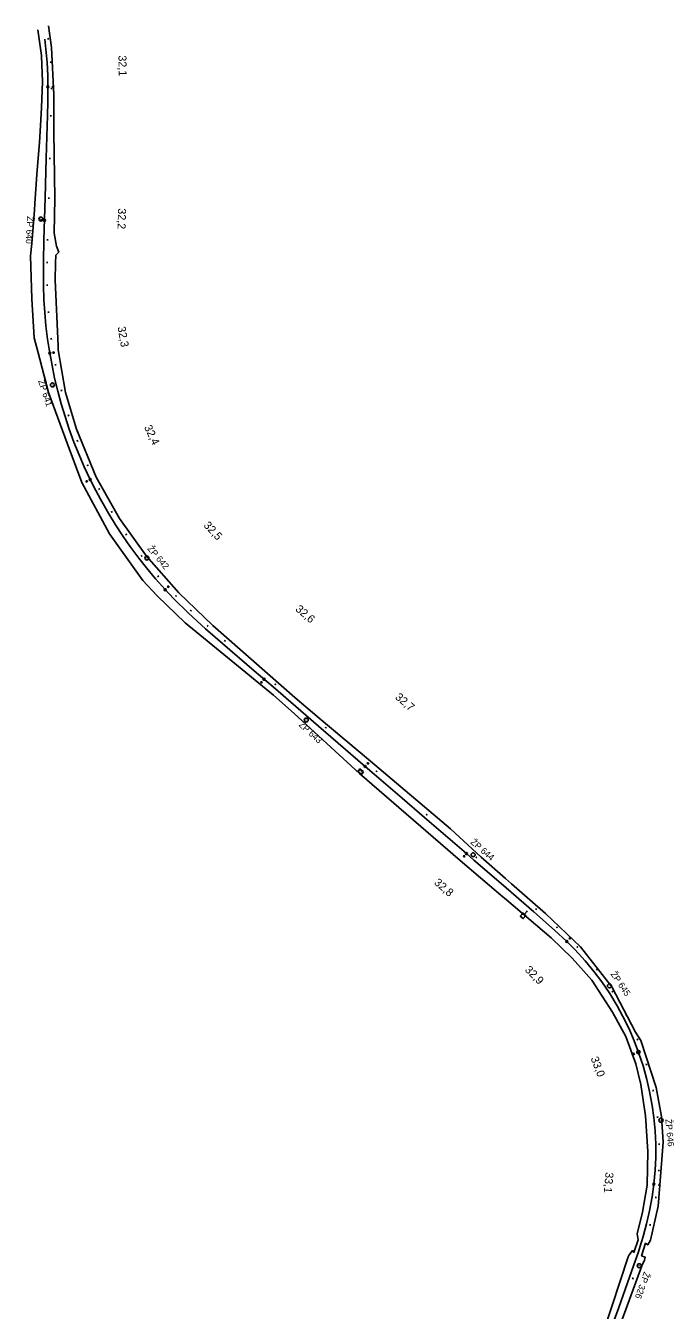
# Model space of a CAD drawing. Extents: x -792643 to -787072, y -1118436 to -1109677.
# Drawn here: x -787716 to -787231, y -1117454 to -1116491 of the extents above; entities that cross this region are included whole.
import ezdxf

# ---------------------------------------------------------------- set-up
doc = ezdxf.new("R2010")
doc.units = 0
for name, color, linetype in [('Vrstva 1', 7, 'Continuous'), ('Vrstva 53', 7, 'Continuous'), ('Vrstva 55', 7, 'Continuous'), ('Vrstva 63', 7, 'Continuous'), ('Vrstva 7', 7, 'Continuous')]:
    doc.layers.add(name, color=color, linetype=linetype)

msp = doc.modelspace()

# ---------------------------------------------------------------- linework, layer by layer
at = {"layer": 'Vrstva 1'}
msp.add_line((-787264.12, -1117429.53), (-787272.21, -1117452.2), dxfattribs=at)
for points in [[(-787702.18, -1116501.52), (-787700.37, -1116518.85), (-787699.93, -1116528.64), (-787699.81, -1116538.53), (-787699.9, -1116548.48), (-787700.14, -1116558.8)], [(-787700.14, -1116558.8), (-787701.09, -1116590.8), (-787701.94, -1116620.53), (-787702.8, -1116651.97)], [(-787702.8, -1116651.97), (-787702.84, -1116653.48), (-787703.18, -1116666.81), (-787703.22, -1116669.06), (-787703.26, -1116685.94), (-787702.88, -1116697), (-787702.25, -1116706.46), (-787701.32, -1116716.33), (-787700.07, -1116726.36), (-787698.93, -1116733.97), (-787696.77, -1116746.1), (-787694.79, -1116755.5), (-787692.39, -1116765.45), (-787689.88, -1116774.8), (-787687.02, -1116784.34), (-787683.84, -1116793.91), (-787680.3, -1116803.58), (-787676.47, -1116813.13), (-787672.58, -1116822.08), (-787668.1, -1116831.64), (-787663.92, -1116839.94), (-787660.46, -1116846.44), (-787654.27, -1116857.3), (-787649.16, -1116865.61), (-787643.47, -1116874.28), (-787638.38, -1116881.6), (-787631.78, -1116890.55), (-787626.01, -1116897.89), (-787619.29, -1116905.95), (-787612.03, -1116914.14), (-787605.82, -1116920.75), (-787594.64, -1116931.83), (-787581.88, -1116943.43), (-787568.99, -1116954.58)], [(-787568.99, -1116954.58), (-787545.21, -1116975.07), (-787531.21, -1116987.13), (-787493.36, -1117019.73), (-787462.15, -1117046.64), (-787455.43, -1117052.44), (-787434.55, -1117070.45)], [(-787434.55, -1117070.45), (-787417.79, -1117084.91), (-787386.34, -1117112.07), (-787380.69, -1117116.94), (-787379.22, -1117118.21), (-787360.32, -1117134.51), (-787335.87, -1117155.61)], [(-787335.87, -1117155.61), (-787320.24, -1117169.32), (-787311.1, -1117177.88), (-787305.04, -1117183.97)], [(-787305.04, -1117183.97), (-787297.25, -1117192.53), (-787290.61, -1117200.61), (-787284.88, -1117208.27), (-787278.99, -1117216.98), (-787273.48, -1117226.04), (-787269.09, -1117234.07), (-787264.5, -1117243.47), (-787260.63, -1117252.4), (-787257.3, -1117261.11), (-787254.01, -1117271.02), (-787251.16, -1117281.27), (-787249.1, -1117290.26), (-787247.17, -1117300.81), (-787245.92, -1117309.87), (-787244.98, -1117319.95), (-787244.5, -1117329.87), (-787244.47, -1117339.84), (-787244.88, -1117349.45), (-787245.82, -1117359.92), (-787247.11, -1117369.4), (-787249.03, -1117379.86), (-787251.29, -1117389.69)], [(-787251.29, -1117389.69), (-787253.84, -1117398.97), (-787255.09, -1117403.11), (-787257.72, -1117411.27), (-787259.63, -1117416.84), (-787264.12, -1117429.53)], [(-787272.21, -1117452.2), (-787280.56, -1117475.36), (-787286.2, -1117490.98), (-787292.86, -1117509.71)]]:
    msp.add_lwpolyline(points, dxfattribs=at)
at = {"layer": 'Vrstva 53'}
for points in [[(-787458.26, -1117042.74), (-787398.26, -1117093.36), (-787375.17, -1117114.73), (-787356.91, -1117130.76), (-787352.43, -1117134.69), (-787327.03, -1117156.98), (-787300.85, -1117181.82), (-787277.47, -1117212.02), (-787259.63, -1117245.84), (-787255.58, -1117252.15), (-787244.19, -1117287.3), (-787240.18, -1117309.09), (-787238.86, -1117328.3), (-787241.48, -1117360.62), (-787242.61, -1117376.43), (-787248.32, -1117401.92), (-787250.51, -1117405.41), (-787252.11, -1117404.13), (-787255.1, -1117413.5), (-787252.33, -1117414.61), (-787252.97, -1117416.89), (-787254.84, -1117421.14), (-787272.47, -1117468.81)], [(-787283.43, -1117469.91), (-787265.1, -1117414.39), (-787264.26, -1117412.91), (-787261.83, -1117409.67), (-787260.78, -1117411.06), (-787257.76, -1117401.7), (-787258.37, -1117397.06), (-787254.36, -1117380.85), (-787250.96, -1117360.68), (-787250.41, -1117335.48), (-787252.03, -1117308.63), (-787255.71, -1117285.12), (-787259.39, -1117269.6), (-787266.99, -1117249.13), (-787276.75, -1117230.94), (-787292.44, -1117206.89), (-787307.2, -1117190.47), (-787322.75, -1117175.25), (-787356.33, -1117146.67), (-787360.49, -1117143.13), (-787390.97, -1117117.19), (-787466.48, -1117052.03)]]:
    msp.add_lwpolyline(points, dxfattribs=at)
at = {"layer": 'Vrstva 55'}
for points in [[(-787466.48, -1117052.03), (-787515.44, -1117007.08), (-787530.85, -1116993.38), (-787597.14, -1116938.99), (-787618.03, -1116918.91), (-787628.62, -1116907.25), (-787653.7, -1116872.34), (-787674.36, -1116833.72), (-787685.49, -1116804.26), (-787699.48, -1116766.3), (-787707.44, -1116735.64), (-787710.11, -1116725.38), (-787711.8, -1116696.13), (-787713, -1116663.97), (-787711.9, -1116654.76), (-787709.96, -1116629.67), (-787709.58, -1116624.69), (-787708.57, -1116610.15), (-787708.05, -1116602.7), (-787706.23, -1116578.86), (-787705.09, -1116561.9), (-787704.56, -1116552.61), (-787703.91, -1116533.48), (-787704.1, -1116526.68), (-787704.38, -1116520.92), (-787704.74, -1116513.73), (-787707.44, -1116494.38)], [(-787699.35, -1116491.37), (-787697.17, -1116507.73), (-787695.53, -1116543.16), (-787695.36, -1116571.42), (-787694.77, -1116620.61), (-787695.13, -1116646.88), (-787693.44, -1116656.57), (-787691.68, -1116661.08), (-787693.98, -1116663.52), (-787694.14, -1116669.51), (-787694.47, -1116681.92), (-787692.19, -1116731.59), (-787692.06, -1116734.36), (-787686.63, -1116766.25), (-787678.51, -1116793.87), (-787663.57, -1116829.76), (-787646.12, -1116860.74), (-787626.1, -1116888.93), (-787601.65, -1116916.45), (-787576.19, -1116941.14), (-787514.87, -1116995.01), (-787496.65, -1117010.38), (-787458.26, -1117042.74)]]:
    msp.add_lwpolyline(points, dxfattribs=at)
at = {"layer": 'Vrstva 63'}
for p, q in [((-787705.09, -1116636.24), (-787705.1, -1116636.44)), ((-787696.48, -1116760.62), (-787696.43, -1116760.82)), ((-787625.76, -1116890.39), (-787625.64, -1116890.55)), ((-787506.41, -1117011.83), (-787506.26, -1117011.96)), ((-787381.34, -1117112.86), (-787381.19, -1117112.99)), ((-787279.17, -1117211.07), (-787279.06, -1117211.24)), ((-787240.55, -1117311.83), (-787240.53, -1117312.03)), ((-787256.83, -1117420.89), (-787256.9, -1117421.08))]:
    msp.add_line(p, q, dxfattribs=at)
for centre in [(-787705.1, -1116636.34), (-787696.46, -1116760.72), (-787625.7, -1116890.47), (-787506.33, -1117011.89), (-787381.26, -1117112.92), (-787279.11, -1117211.15), (-787240.54, -1117311.93), (-787256.87, -1117420.99)]:
    msp.add_circle(centre, 1.51, dxfattribs=at)
at = {"layer": 'Vrstva 7'}
for p, q in [((-787699.05, -1116501.06), (-787700.05, -1116501.17)), ((-787699.6, -1116500.62), (-787699.5, -1116501.61)), ((-787697.2, -1116518.63), (-787698.19, -1116518.67)), ((-787697.72, -1116518.15), (-787697.67, -1116519.15)), ((-787696.7, -1116538.54), (-787697.7, -1116538.53)), ((-787697.19, -1116538.03), (-787697.2, -1116539.03)), ((-787695.98, -1116537.12), (-787695.98, -1116537.22)), ((-787697.09, -1116558.9), (-787698.09, -1116558.87)), ((-787697.58, -1116558.38), (-787697.61, -1116559.38)), ((-787697.96, -1116590.88), (-787698.96, -1116590.85)), ((-787698.45, -1116590.37), (-787698.48, -1116591.37)), ((-787698.73, -1116620.58), (-787699.73, -1116620.55)), ((-787699.22, -1116620.06), (-787699.25, -1116621.06)), ((-787704.65, -1116637.2), (-787704.65, -1116637.3)), ((-787699.57, -1116652.04), (-787700.57, -1116652.02)), ((-787700.06, -1116651.53), (-787700.08, -1116652.53)), ((-787699.97, -1116669), (-787700.97, -1116668.99)), ((-787700.47, -1116668.5), (-787700.47, -1116669.5)), ((-787699.98, -1116685.94), (-787700.98, -1116685.98)), ((-787700.5, -1116685.46), (-787700.47, -1116686.46)), ((-787698.98, -1116706.19), (-787699.97, -1116706.29)), ((-787699.52, -1116705.74), (-787699.43, -1116706.74)), ((-787696.83, -1116725.96), (-787697.82, -1116726.1)), ((-787697.4, -1116725.54), (-787697.25, -1116726.52)), ((-787695.62, -1116736.41), (-787695.61, -1116736.5)), ((-787693.63, -1116745.45), (-787694.62, -1116745.63)), ((-787694.21, -1116745.05), (-787694.04, -1116746.03)), ((-787689.28, -1116764.67), (-787690.25, -1116764.93)), ((-787689.9, -1116764.31), (-787689.64, -1116765.28)), ((-787683.92, -1116783.36), (-787684.87, -1116783.68)), ((-787684.55, -1116783.04), (-787684.24, -1116783.99)), ((-787677.29, -1116802.42), (-787678.23, -1116802.76)), ((-787677.93, -1116802.12), (-787677.59, -1116803.06)), ((-787669.62, -1116820.76), (-787670.53, -1116821.18)), ((-787670.29, -1116820.52), (-787669.87, -1116821.43)), ((-787670.83, -1116832.97), (-787670.78, -1116833.06)), ((-787661.09, -1116838.48), (-787661.97, -1116838.95)), ((-787661.77, -1116838.27), (-787661.3, -1116839.16)), ((-787651.51, -1116855.66), (-787652.36, -1116856.18)), ((-787652.2, -1116855.5), (-787651.68, -1116856.35)), ((-787640.81, -1116872.47), (-787641.65, -1116873.02)), ((-787641.51, -1116872.33), (-787640.96, -1116873.17)), ((-787629.23, -1116888.56), (-787630.04, -1116889.15)), ((-787629.93, -1116888.45), (-787629.34, -1116889.26)), ((-787616.85, -1116903.86), (-787617.62, -1116904.5)), ((-787617.55, -1116903.79), (-787616.91, -1116904.56)), ((-787609.7, -1116911.97), (-787609.63, -1116912.04)), ((-787603.52, -1116918.46), (-787604.24, -1116919.14)), ((-787604.22, -1116918.44), (-787603.54, -1116919.17)), ((-787593.12, -1116929.51), (-787592.38, -1116930.19)), ((-787592.41, -1116929.48), (-787593.08, -1116930.22)), ((-787580.46, -1116940.98), (-787579.72, -1116941.65)), ((-787580.46, -1116940.98), (-787579.72, -1116941.65)), ((-787579.76, -1116940.95), (-787580.43, -1116941.69)), ((-787579.76, -1116940.95), (-787580.43, -1116941.69)), ((-787567.65, -1116952.2), (-787566.9, -1116952.85)), ((-787567.65, -1116952.2), (-787566.9, -1116952.85)), ((-787566.95, -1116952.15), (-787567.6, -1116952.91)), ((-787566.95, -1116952.15), (-787567.6, -1116952.91)), ((-787539.88, -1116983.58), (-787539.8, -1116983.64)), ((-787529.79, -1116984.78), (-787529.04, -1116985.43)), ((-787529.09, -1116984.73), (-787529.74, -1116985.48)), ((-787492.03, -1117017.35), (-787491.28, -1117018.01)), ((-787491.33, -1117017.3), (-787491.98, -1117018.06)), ((-787464.32, -1117049.17), (-787464.73, -1117049.65)), ((-787460.13, -1117044.33), (-787460.06, -1117044.39)), ((-787454.02, -1117049.96), (-787453.27, -1117050.61)), ((-787453.32, -1117049.91), (-787453.97, -1117050.67)), ((-787416.4, -1117082.55), (-787415.64, -1117083.2)), ((-787415.69, -1117082.5), (-787416.35, -1117083.25)), ((-787388.04, -1117113.97), (-787387.96, -1117114.04)), ((-787379.21, -1117114.58), (-787378.46, -1117115.24)), ((-787378.51, -1117114.53), (-787379.16, -1117115.29)), ((-787342.87, -1117157.54), (-787340.92, -1117155.26)), ((-787340.54, -1117155.59), (-787341.3, -1117154.94)), ((-787334.45, -1117153.38), (-787333.67, -1117154.01)), ((-787333.74, -1117153.31), (-787334.37, -1117154.08)), ((-787318.76, -1117166.95), (-787318.03, -1117167.63)), ((-787318.06, -1117166.93), (-787318.74, -1117167.65)), ((-787308.88, -1117175.51), (-787308.81, -1117175.58)), ((-787302.76, -1117181.72), (-787303.47, -1117182.43)), ((-787303.47, -1117181.72), (-787302.76, -1117182.43)), ((-787288.11, -1117198.64), (-787288.91, -1117199.24)), ((-787288.81, -1117198.54), (-787288.21, -1117199.34)), ((-787276.38, -1117215.21), (-787277.21, -1117215.77)), ((-787277.07, -1117215.07), (-787276.51, -1117215.9)), ((-787266.26, -1117232.64), (-787267.16, -1117233.08)), ((-787266.93, -1117232.41), (-787266.49, -1117233.31)), ((-787257.72, -1117251.11), (-787258.63, -1117251.51)), ((-787258.37, -1117250.85), (-787257.98, -1117251.77)), ((-787260.95, -1117262.14), (-787260.92, -1117262.24)), ((-787250.98, -1117270.06), (-787251.94, -1117270.33)), ((-787251.59, -1117269.71), (-787251.32, -1117270.68)), ((-787245.93, -1117289.65), (-787246.91, -1117289.83)), ((-787246.51, -1117289.25), (-787246.33, -1117290.23)), ((-787243.26, -1117309.01), (-787243.17, -1117310)), ((-787242.72, -1117309.46), (-787243.71, -1117309.55)), ((-787241.3, -1117329.77), (-787242.3, -1117329.77)), ((-787241.81, -1117329.27), (-787241.8, -1117330.27)), ((-787241.67, -1117349.69), (-787242.66, -1117349.6)), ((-787242.12, -1117349.15), (-787242.21, -1117350.15)), ((-787241.63, -1117360.35), (-787241.64, -1117360.45)), ((-787243.92, -1117369.87), (-787244.9, -1117369.69)), ((-787244.32, -1117369.29), (-787244.5, -1117370.27)), ((-787248.18, -1117390.55), (-787249.14, -1117390.29)), ((-787248.53, -1117389.94), (-787248.79, -1117390.9)), ((-787261.12, -1117430.64), (-787262.06, -1117430.3)), ((-787261.09, -1117430.58), (-787262.03, -1117430.24)), ((-787261.43, -1117430), (-787261.76, -1117430.94)), ((-787261.39, -1117429.94), (-787261.73, -1117430.88))]:
    msp.add_line(p, q, dxfattribs=at)
msp.add_lwpolyline([(-787463.41, -1117050.78), (-787465.03, -1117052.66), (-787467.67, -1117050.38), (-787466.05, -1117048.5)], close=True, dxfattribs=at)
for points in [[(-787342.87, -1117157.54), (-787344.01, -1117156.56), (-787345.96, -1117158.84), (-787343.69, -1117160.79), (-787341.73, -1117158.51), (-787342.87, -1117157.54)], [(-787342.39, -1117159.27), (-787342.87, -1117157.54), (-787344.66, -1117157.32)]]:
    msp.add_lwpolyline(points, dxfattribs=at)
for centre, radius in [((-787699.82, -1116537.22), 0.75), ((-787695.98, -1116537.17), 0.5), ((-787704.65, -1116637.25), 0.5), ((-787702.4, -1116637.31), 0.75), ((-787698.4, -1116736.96), 0.75), ((-787695.61, -1116736.46), 0.5), ((-787670.8, -1116833.02), 0.5), ((-787668.1, -1116831.65), 0.75), ((-787611.99, -1116914.19), 0.75), ((-787609.67, -1116912.01), 0.5), ((-787537.9, -1116981.36), 0.75), ((-787539.84, -1116983.61), 0.5), ((-787462.1, -1117046.69), 0.75), ((-787460.09, -1117044.36), 0.5), ((-787388, -1117114.01), 0.5), ((-787386.33, -1117112.07), 0.75), ((-787311.1, -1117177.88), 0.75), ((-787308.84, -1117175.55), 0.5), ((-787257.4, -1117260.83), 1.25), ((-787257.4, -1117260.83), 0.752), ((-787260.94, -1117262.19), 0.5), ((-787245.82, -1117359.92), 0.75), ((-787241.64, -1117360.4), 0.5)]:
    msp.add_circle(centre, radius, dxfattribs=at)

# ---------------------------------------------------------------- texts
at = {"layer": 'Vrstva 63'}
for s, rotation, p in [('ŽP 640', 267, (-787715.38, -1116634.11)), ('ŽP 641', 288, (-787707.22, -1116757.67)), ('ŽP 642', 310, (-787625.61, -1116883.64)), ('ŽP 643', 318, (-787512.37, -1117015.99)), ('ŽP 644', 319.21928, (-787383.66, -1117104.11)), ('ŽP 645', 304.09803, (-787278.6, -1117202.29)), ('ŽP 646', 275.33133, (-787237.29, -1117311.23)), ('ŽP 326', 250.48017, (-787253.19, -1117425.19))]:
    msp.add_text(s, height=4.8, rotation=rotation, dxfattribs=at).set_placement(p)
at = {"layer": 'Vrstva 7'}
for s, height, rotation, p in [('32,1', 6, 270.71261, (-787647.01, -1116513.66)), ('32,2', 6, 268.43885, (-787647.25, -1116628.23)), ('32,3', 6, 280.11242, (-787647.72, -1116717.33)), ('32,4', 6, 295.08642, (-787627.93, -1116792.29)), ('32,5', 6, 313.20423, (-787583.64, -1116866.31)), ('32,6', 6, 319.26117, (-787514.86, -1116929.49)), ('32,7', 6, 319.22739, (-787440.18, -1116995.49)), ('KM', 1.247, 139.18447, (-787464.36, -1117050.78)), ('32,8', 6, 319.18383, (-787410.98, -1117134.53)), ('32,9', 6, 314.87733, (-787342.95, -1117199.63)), ('33,0', 6, 290.92231, (-787293.35, -1117265.49)), ('33,1', 6, 264.89842, (-787282, -1117350.66))]:
    msp.add_text(s, height=height, rotation=rotation, dxfattribs=at).set_placement(p)

doc.saveas('drawing.dxf')
